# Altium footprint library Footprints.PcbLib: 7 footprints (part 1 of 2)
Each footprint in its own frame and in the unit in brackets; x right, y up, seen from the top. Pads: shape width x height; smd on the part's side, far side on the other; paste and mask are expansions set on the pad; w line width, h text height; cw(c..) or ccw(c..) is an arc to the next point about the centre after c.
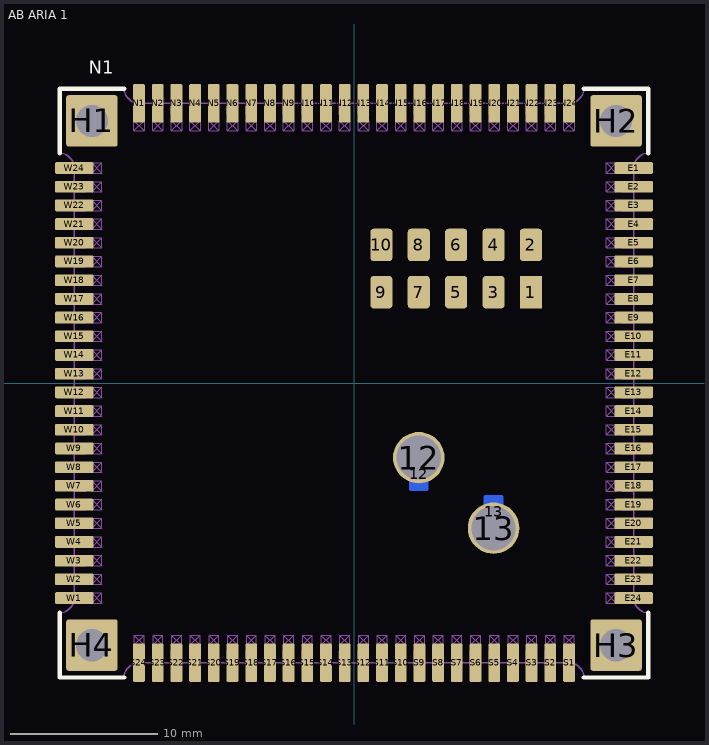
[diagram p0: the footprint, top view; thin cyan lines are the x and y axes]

## AB ARIA 1 [mm]
pads (114):
  rect 1.5x2.2 smd paste-0.2: 1(12.02,6.17)
  rrect30% 1.5x2.2 smd paste-0.2: 2(12.02,9.38) 3(9.48,6.17) 4(9.48,9.38) 5(6.94,6.17) 6(6.94,9.38) 7(4.4,6.17) 8(4.4,9.38) 9(1.86,6.17) 10(1.86,9.38)
  rrect20% 1.3x2.25 smd far side: 12(4.4,-6.195) 13(9.48,-8.735)
  round 3.5 hole 3 paste-1 mask+0.1: 12(4.4,-5.07) 13(9.48,-9.86)
  rrect20% 2.6x0.8 smd paste+0.05: E1(19,14.605) E2(19,13.335) E3(19,12.065) E4(19,10.795) E5(19,9.525) E6(19,8.255) E7(19,6.985) E8(19,5.715) E9(19,4.445) E10(19,3.175) E11(19,1.905) E12(19,0.635) E13(19,-0.635) E14(19,-1.905) E15(19,-3.175) E16(19,-4.445) E17(19,-5.715) E18(19,-6.985) E19(19,-8.255) E20(19,-9.525) E21(19,-10.795) E22(19,-12.065) E23(19,-13.335) E24(19,-14.605) W1(-19,-14.605) W2(-19,-13.335) W3(-19,-12.065) W4(-19,-10.795) W5(-19,-9.525) W6(-19,-8.255) W7(-19,-6.985) W8(-19,-5.715) W9(-19,-4.445) W10(-19,-3.175) W11(-19,-1.905) W12(-19,-0.635) W13(-19,0.635) W14(-19,1.905) W15(-19,3.175) W16(-19,4.445) W17(-19,5.715) W18(-19,6.985) W19(-19,8.255) W20(-19,9.525) W21(-19,10.795) W22(-19,12.065) W23(-19,13.335) W24(-19,14.605)
  rrect10% 3.5x3.5 hole 2.2 mask+0.2: H1(-17.8,17.8) H2(17.8,17.8) H3(17.8,-17.8) H4(-17.8,-17.8)
  rrect20% 0.8x2.6 smd paste+0.05: N1(-14.605,19) N2(-13.335,19) N3(-12.065,19) N4(-10.795,19) N5(-9.525,19) N6(-8.255,19) N7(-6.985,19) N8(-5.715,19) N9(-4.445,19) N10(-3.175,19) N11(-1.905,19) N12(-0.635,19) N13(0.635,19) N14(1.905,19) N15(3.175,19) N16(4.445,19) N17(5.715,19) N18(6.985,19) N19(8.255,19) N20(9.525,19) N21(10.795,19) N22(12.065,19) N23(13.335,19) N24(14.605,19) S1(14.605,-19) S2(13.335,-19) S3(12.065,-19) S4(10.795,-19) S5(9.525,-19) S6(8.255,-19) S7(6.985,-19) S8(5.715,-19) S9(4.445,-19) S10(3.175,-19) S11(1.905,-19) S12(0.635,-19) S13(-0.635,-19) S14(-1.905,-19) S15(-3.175,-19) S16(-4.445,-19) S17(-5.715,-19) S18(-6.985,-19) S19(-8.255,-19) S20(-9.525,-19) S21(-10.795,-19) S22(-12.065,-19) S23(-13.335,-19) S24(-14.605,-19)
Top Overlay:
  lines w0.3: -20,-15.605 -20,-20 ; -20,15.605 -20,20 -15.605,20 ; -15.605,-20 -20,-20 ; 15.605,-20 20,-20 20,-15.605 ; 15.605,20 20,20 ; 20,15.605 20,20 ; -20,-20 -20,-20 ; -15.605,20 -15.605,20 ; 20,20 20,20
  text "N1" at -18.034,20.701 h1.52
Top Paste:
  lines w0.8: -20.75,-14.61 -20.45,-14.61 ; -20.75,-13.34 -20.45,-13.34 ; -20.75,-12.07 -20.45,-12.07 ; -20.75,-10.8 -20.45,-10.8 ; -20.75,-9.53 -20.45,-9.53 ; -20.75,-8.26 -20.45,-8.26 ; -20.75,-6.99 -20.45,-6.99 ; -20.75,-5.72 -20.45,-5.72 ; -20.75,-4.45 -20.45,-4.45 ; -20.75,-3.18 -20.45,-3.18 ; -20.75,-1.91 -20.45,-1.91 ; -20.75,-0.64 -20.45,-0.64 ; -20.75,0.63 -20.45,0.63 ; -20.75,1.9 -20.45,1.9 ; -20.75,3.17 -20.45,3.17 ; -20.75,4.44 -20.45,4.44 ; -20.75,5.71 -20.45,5.71 ; -20.75,6.98 -20.45,6.98 ; -20.75,8.25 -20.45,8.25 ; -20.75,9.52 -20.45,9.52 ; -20.75,10.79 -20.45,10.79 ; -20.75,12.06 -20.45,12.06 ; -20.75,13.33 -20.45,13.33 ; -20.75,14.6 -20.45,14.6 ; -14.61,20.45 -14.61,20.75 ; -14.6,-20.75 -14.6,-20.45 ; -13.34,20.45 -13.34,20.75 ; -13.33,-20.75 -13.33,-20.45 ; -12.07,20.45 -12.07,20.75 ; -12.06,-20.75 -12.06,-20.45 ; -10.8,20.45 -10.8,20.75 ; -10.79,-20.75 -10.79,-20.45 ; -9.53,20.45 -9.53,20.75 ; -9.52,-20.75 -9.52,-20.45 ; -8.26,20.45 -8.26,20.75 ; -8.25,-20.75 -8.25,-20.45 ; -6.99,20.45 -6.99,20.75 ; -6.98,-20.75 -6.98,-20.45 ; -5.72,20.45 -5.72,20.75 ; -5.71,-20.75 -5.71,-20.45 ; -4.45,20.45 -4.45,20.75 ; -4.44,-20.75 -4.44,-20.45 ; -3.18,20.45 -3.18,20.75 ; -3.17,-20.75 -3.17,-20.45 ; -1.91,20.45 -1.91,20.75 ; -1.9,-20.75 -1.9,-20.45 ; -0.64,20.45 -0.64,20.75 ; -0.63,-20.75 -0.63,-20.45 ; 0.63,20.45 0.63,20.75 ; 0.64,-20.75 0.64,-20.45 ; 1.9,20.45 1.9,20.75 ; 1.91,-20.75 1.91,-20.45 ; 3.17,20.45 3.17,20.75 ; 3.18,-20.75 3.18,-20.45 ; 4.44,20.45 4.44,20.75 ; 4.45,-20.75 4.45,-20.45 ; 5.71,20.45 5.71,20.75 ; 5.72,-20.75 5.72,-20.45 ; 6.98,20.45 6.98,20.75 ; 6.99,-20.75 6.99,-20.45 ; 8.25,20.45 8.25,20.75 ; 8.26,-20.75 8.26,-20.45 ; 9.52,20.45 9.52,20.75 ; 9.53,-20.75 9.53,-20.45 ; 10.79,20.45 10.79,20.75 ; 10.8,-20.75 10.8,-20.45 ; 12.06,20.45 12.06,20.75 ; 12.07,-20.75 12.07,-20.45 ; 13.33,20.45 13.33,20.75 ; 13.34,-20.75 13.34,-20.45 ; 14.6,20.45 14.6,20.75 ; 14.61,-20.75 14.61,-20.45 ; 20.45,-14.6 20.75,-14.6 ; 20.45,-13.33 20.75,-13.33 ; 20.45,-12.06 20.75,-12.06 ; 20.45,-10.79 20.75,-10.79 ; 20.45,-9.52 20.75,-9.52 ; 20.45,-8.25 20.75,-8.25 ; 20.45,-6.98 20.75,-6.98 ; 20.45,-5.71 20.75,-5.71 ; 20.45,-4.44 20.75,-4.44 ; 20.45,-3.17 20.75,-3.17 ; 20.45,-1.9 20.75,-1.9 ; 20.45,-0.63 20.75,-0.63 ; 20.45,0.64 20.75,0.64 ; 20.45,1.91 20.75,1.91 ; 20.45,3.18 20.75,3.18 ; 20.45,4.45 20.75,4.45 ; 20.45,5.72 20.75,5.72 ; 20.45,6.99 20.75,6.99 ; 20.45,8.26 20.75,8.26 ; 20.45,9.53 20.75,9.53 ; 20.45,10.8 20.75,10.8 ; 20.45,12.07 20.75,12.07 ; 20.45,13.34 20.75,13.34 ; 20.45,14.61 20.75,14.61
Bottom Solder:
  region: 10.155,7.199 8.79,7.199 8.79,5.161 10.155,5.161
  region: 10.164,10.397 8.799,10.397 8.799,8.359 10.164,8.359
  region: 12.701,10.397 11.336,10.397 11.336,8.359 12.701,8.359
Mechanical 1:
  lines w0.1: 14.605,-19 cw(c14.605,-20) 15.605,-20 20,-20 20,-15.605 cw(c20,-14.605) 19,-14.605 19,14.605 cw(c20,14.605) 20,15.605 20,20 15.605,20 cw(c14.605,20) 14.605,19 -14.605,19 cw(c-14.605,20) -15.605,20 -20,20 -20,15.605 cw(c-20,14.605) -19,14.605 -19,-14.605 cw(c-20,-14.605) -20,-15.605 -20,-20 -15.605,-20 cw(c-14.605,-20) -14.605,-19 14.655,-19
Mechanical 15:
  drawing of 1308 lines, arcs and shapes, not listed
3D body "Aria.step": height 2.75, standoff 0.01, extent -20.055,-20.055 20.054,20.054
3D body: height 0.02, standoff -0.03, extent 8.786,-9.433 10.18,-8.036
3D body: height 0.02, standoff -0.03, extent 3.706,-6.893 5.1,-5.496
3D body: height 0.1, standoff 0.01, extent 1.21,5.17 2.51,7.17
3D body: height 0.1, standoff 0.01, extent 3.75,5.17 5.05,7.17
3D body: height 0.1, standoff 0.01, extent 6.29,5.17 7.59,7.17
3D body: height 0.1, standoff 0.01, extent 8.83,5.17 10.13,7.17
3D body: height 0.1, standoff 0.01, extent 11.37,5.17 12.67,7.17
3D body: height 0.1, standoff 0.01, extent 1.21,8.38 2.51,10.38
3D body: height 0.1, standoff 0.01, extent 3.75,8.38 5.05,10.38
3D body: height 0.1, standoff 0.01, extent 6.29,8.38 7.59,10.38
3D body: height 0.1, standoff 0.01, extent 8.83,8.38 10.13,10.38
3D body: height 0.1, standoff 0.01, extent 11.37,8.38 12.67,10.38
3D body: height 1.51, standoff 0.01, extent -0.64,13.7 0.72,15.27
3D body: height 1.51, standoff 0.01, extent -1.599,16 1.6,17.6
3D body: height 1.51, standoff 1.4, extent 17.82,14.255 19.05,14.955
3D body: height 0.1, standoff 0.01, extent 17.12,14.255 17.82,14.955
3D body: height 1.4, standoff 0.01, extent 18.23,14.255 19.05,14.955
3D body: height 1.4, standoff 0.01, extent 18.23,12.985 19.05,13.685
3D body: height 0.1, standoff 0.01, extent 17.12,12.985 17.82,13.685
3D body: height 1.51, standoff 1.4, extent 18.23,12.985 19.05,13.685
3D body: height 1.4, standoff 0.01, extent 18.23,11.715 19.05,12.415
3D body: height 0.1, standoff 0.01, extent 17.12,11.715 17.82,12.415
3D body: height 1.51, standoff 1.4, extent 18.23,11.715 19.05,12.415
3D body: height 1.4, standoff 0.01, extent 18.23,10.445 19.05,11.145
3D body: height 0.1, standoff 0.01, extent 17.12,10.445 17.82,11.145
3D body: height 1.51, standoff 1.4, extent 18.23,10.445 19.05,11.145
3D body: height 1.4, standoff 0.01, extent 18.23,9.175 19.05,9.875
3D body: height 0.1, standoff 0.01, extent 17.12,9.175 17.82,9.875
3D body: height 1.51, standoff 1.4, extent 18.23,9.175 19.05,9.875
3D body: height 1.4, standoff 0.01, extent 18.23,7.905 19.05,8.605
3D body: height 0.1, standoff 0.01, extent 17.12,7.905 17.82,8.605
3D body: height 1.51, standoff 1.4, extent 18.23,7.905 19.05,8.605
3D body: height 1.4, standoff 0.01, extent 18.23,6.635 19.05,7.335
3D body: height 0.1, standoff 0.01, extent 17.12,6.635 17.82,7.335
3D body: height 1.51, standoff 1.4, extent 18.23,6.635 19.05,7.335
3D body: height 1.4, standoff 0.01, extent 18.23,5.365 19.05,6.065
3D body: height 0.1, standoff 0.01, extent 17.12,5.365 17.82,6.065
3D body: height 1.51, standoff 1.4, extent 18.23,5.365 19.05,6.065
3D body: height 1.4, standoff 0.01, extent 18.23,4.095 19.05,4.795
3D body: height 0.1, standoff 0.01, extent 17.12,4.095 17.82,4.795
3D body: height 1.51, standoff 1.4, extent 18.23,4.095 19.05,4.795
3D body: height 1.4, standoff 0.01, extent 18.23,2.825 19.05,3.525
3D body: height 0.1, standoff 0.01, extent 17.12,2.825 17.82,3.525
3D body: height 1.51, standoff 1.4, extent 18.23,2.825 19.05,3.525
3D body: height 1.4, standoff 0.01, extent 18.23,1.555 19.05,2.255
3D body: height 0.1, standoff 0.01, extent 17.12,1.555 17.82,2.255
3D body: height 1.51, standoff 1.4, extent 18.23,1.555 19.05,2.255
3D body: height 1.4, standoff 0.01, extent 18.23,0.285 19.05,0.985
3D body: height 0.1, standoff 0.01, extent 17.12,0.285 17.82,0.985
3D body: height 1.51, standoff 1.4, extent 18.23,0.285 19.05,0.985
3D body: height 1.4, standoff 0.01, extent 18.23,-0.985 19.05,-0.285
3D body: height 0.1, standoff 0.01, extent 17.12,-0.985 17.82,-0.285
3D body: height 1.51, standoff 1.4, extent 18.23,-0.985 19.05,-0.285
3D body: height 1.4, standoff 0.01, extent 18.23,-2.255 19.05,-1.555
3D body: height 0.1, standoff 0.01, extent 17.12,-2.255 17.82,-1.555
3D body: height 1.51, standoff 1.4, extent 18.23,-2.255 19.05,-1.555
3D body: height 1.4, standoff 0.01, extent 18.23,-3.525 19.05,-2.825
3D body: height 0.1, standoff 0.01, extent 17.12,-3.525 17.82,-2.825
3D body: height 1.51, standoff 1.4, extent 18.23,-3.525 19.05,-2.825
3D body: height 1.4, standoff 0.01, extent 18.23,-4.795 19.05,-4.095
3D body: height 0.1, standoff 0.01, extent 17.12,-4.795 17.82,-4.095
3D body: height 1.51, standoff 1.4, extent 18.23,-4.795 19.05,-4.095
3D body: height 1.4, standoff 0.01, extent 18.23,-6.065 19.05,-5.365
3D body: height 0.1, standoff 0.01, extent 17.12,-6.065 17.82,-5.365
3D body: height 1.51, standoff 1.4, extent 18.23,-6.065 19.05,-5.365
3D body: height 1.4, standoff 0.01, extent 18.23,-7.335 19.05,-6.635
3D body: height 0.1, standoff 0.01, extent 17.12,-7.335 17.82,-6.635
3D body: height 1.51, standoff 1.4, extent 18.23,-7.335 19.05,-6.635
3D body: height 1.4, standoff 0.01, extent 18.23,-8.605 19.05,-7.905
3D body: height 0.1, standoff 0.01, extent 17.12,-8.605 17.82,-7.905
3D body: height 1.51, standoff 1.4, extent 18.23,-8.605 19.05,-7.905
3D body: height 1.4, standoff 0.01, extent 18.23,-9.875 19.05,-9.175
3D body: height 0.1, standoff 0.01, extent 17.12,-9.875 17.82,-9.175
3D body: height 1.51, standoff 1.4, extent 18.23,-9.875 19.05,-9.175
3D body: height 1.4, standoff 0.01, extent 18.23,-11.145 19.05,-10.445
3D body: height 0.1, standoff 0.01, extent 17.12,-11.145 17.82,-10.445
3D body: height 1.51, standoff 1.4, extent 18.23,-11.145 19.05,-10.445
3D body: height 1.4, standoff 0.01, extent 18.23,-12.415 19.05,-11.715
3D body: height 0.1, standoff 0.01, extent 17.12,-12.415 17.82,-11.715
3D body: height 1.51, standoff 1.4, extent 18.23,-12.415 19.05,-11.715
3D body: height 1.4, standoff 0.01, extent 18.23,-13.685 19.05,-12.985
3D body: height 0.1, standoff 0.01, extent 17.12,-13.685 17.82,-12.985
3D body: height 1.51, standoff 1.4, extent 18.23,-13.685 19.05,-12.985
3D body: height 1.4, standoff 0.01, extent 18.23,-14.955 19.05,-14.255
3D body: height 0.1, standoff 0.01, extent 17.12,-14.955 17.82,-14.255
3D body: height 1.51, standoff 1.4, extent 18.23,-14.955 19.05,-14.255
3D body: height 1.4, standoff 0.01, extent 14.255,-19.05 14.955,-18.23
3D body: height 0.1, standoff 0.01, extent 14.255,-17.82 14.955,-17.12
3D body: height 1.51, standoff 1.4, extent 14.255,-19.05 14.955,-17.82
3D body: height 1.4, standoff 0.01, extent 12.985,-19.05 13.685,-18.23
3D body: height 0.1, standoff 0.01, extent 12.985,-17.82 13.685,-17.12
3D body: height 1.51, standoff 1.4, extent 12.985,-19.05 13.685,-18.23
3D body: height 1.4, standoff 0.01, extent 11.715,-19.05 12.415,-18.23
3D body: height 0.1, standoff 0.01, extent 11.715,-17.82 12.415,-17.12
3D body: height 1.51, standoff 1.4, extent 11.715,-19.05 12.415,-18.23
3D body: height 1.4, standoff 0.01, extent 10.445,-19.05 11.145,-18.23
3D body: height 0.1, standoff 0.01, extent 10.445,-17.82 11.145,-17.12
3D body: height 1.51, standoff 1.4, extent 10.445,-19.05 11.145,-18.23
3D body: height 1.4, standoff 0.01, extent 9.175,-19.05 9.875,-18.23
3D body: height 0.1, standoff 0.01, extent 9.175,-17.82 9.875,-17.12
3D body: height 1.51, standoff 1.4, extent 9.175,-19.05 9.875,-18.23
3D body: height 1.4, standoff 0.01, extent 7.905,-19.05 8.605,-18.23
3D body: height 0.1, standoff 0.01, extent 7.905,-17.82 8.605,-17.12
3D body: height 1.51, standoff 1.4, extent 7.905,-19.05 8.605,-18.23
3D body: height 1.4, standoff 0.01, extent 6.635,-19.05 7.335,-18.23
3D body: height 0.1, standoff 0.01, extent 6.635,-17.82 7.335,-17.12
3D body: height 1.51, standoff 1.4, extent 6.635,-19.05 7.335,-18.23
3D body: height 1.4, standoff 0.01, extent 5.365,-19.05 6.065,-18.23
3D body: height 0.1, standoff 0.01, extent 5.365,-17.82 6.065,-17.12
3D body: height 1.51, standoff 1.4, extent 5.365,-19.05 6.065,-18.23
3D body: height 1.4, standoff 0.01, extent 4.095,-19.05 4.795,-18.23
3D body: height 0.1, standoff 0.01, extent 4.095,-17.82 4.795,-17.12
3D body: height 1.51, standoff 1.4, extent 4.095,-19.05 4.795,-18.23
3D body: height 1.4, standoff 0.01, extent 2.825,-19.05 3.525,-18.23
3D body: height 0.1, standoff 0.01, extent 2.825,-17.82 3.525,-17.12
3D body: height 1.51, standoff 1.4, extent 2.825,-19.05 3.525,-18.23
3D body: height 1.4, standoff 0.01, extent 1.555,-19.05 2.255,-18.23
3D body: height 0.1, standoff 0.01, extent 1.555,-17.82 2.255,-17.12
3D body: height 1.51, standoff 1.4, extent 1.555,-19.05 2.255,-18.23
3D body: height 1.4, standoff 0.01, extent 0.285,-19.05 0.985,-18.23
3D body: height 0.1, standoff 0.01, extent 0.285,-17.82 0.985,-17.12
3D body: height 1.51, standoff 1.4, extent 0.285,-19.05 0.985,-18.23
3D body: height 1.4, standoff 0.01, extent -0.985,-19.05 -0.285,-18.23
3D body: height 0.1, standoff 0.01, extent -0.985,-17.82 -0.285,-17.12
3D body: height 1.51, standoff 1.4, extent -0.985,-19.05 -0.285,-18.23
3D body: height 1.4, standoff 0.01, extent -2.255,-19.05 -1.555,-18.23
3D body: height 0.1, standoff 0.01, extent -2.255,-17.82 -1.555,-17.12
3D body: height 1.51, standoff 1.4, extent -2.255,-19.05 -1.555,-18.23
3D body: height 1.4, standoff 0.01, extent -3.525,-19.05 -2.825,-18.23
3D body: height 0.1, standoff 0.01, extent -3.525,-17.82 -2.825,-17.12
3D body: height 1.51, standoff 1.4, extent -3.525,-19.05 -2.825,-18.23
3D body: height 1.4, standoff 0.01, extent -4.795,-19.05 -4.095,-18.23
3D body: height 0.1, standoff 0.01, extent -4.795,-17.82 -4.095,-17.12
3D body: height 1.51, standoff 1.4, extent -4.795,-19.05 -4.095,-18.23
3D body: height 1.4, standoff 0.01, extent -6.065,-19.05 -5.365,-18.23
3D body: height 0.1, standoff 0.01, extent -6.065,-17.82 -5.365,-17.12
3D body: height 1.51, standoff 1.4, extent -6.065,-19.05 -5.365,-18.23
3D body: height 1.4, standoff 0.01, extent -7.335,-19.05 -6.635,-18.23
3D body: height 0.1, standoff 0.01, extent -7.335,-17.82 -6.635,-17.12
3D body: height 1.51, standoff 1.4, extent -7.335,-19.05 -6.635,-18.23
3D body: height 1.4, standoff 0.01, extent -8.605,-19.05 -7.905,-18.23
3D body: height 0.1, standoff 0.01, extent -8.605,-17.82 -7.905,-17.12
3D body: height 1.51, standoff 1.4, extent -8.605,-19.05 -7.905,-18.23
3D body: height 1.4, standoff 0.01, extent -9.875,-19.05 -9.175,-18.23
3D body: height 0.1, standoff 0.01, extent -9.875,-17.82 -9.175,-17.12
3D body: height 1.51, standoff 1.4, extent -9.875,-19.05 -9.175,-18.23
3D body: height 1.4, standoff 0.01, extent -11.145,-19.05 -10.445,-18.23
3D body: height 0.1, standoff 0.01, extent -11.145,-17.82 -10.445,-17.12
3D body: height 1.51, standoff 1.4, extent -11.145,-19.05 -10.445,-18.23
3D body: height 1.4, standoff 0.01, extent -12.415,-19.05 -11.715,-18.23
3D body: height 0.1, standoff 0.01, extent -12.415,-17.82 -11.715,-17.12
3D body: height 1.51, standoff 1.4, extent -12.415,-19.05 -11.715,-18.23
3D body: height 1.4, standoff 0.01, extent -13.685,-19.05 -12.985,-18.23
3D body: height 0.1, standoff 0.01, extent -13.685,-17.82 -12.985,-17.12
3D body: height 1.51, standoff 1.4, extent -13.685,-19.05 -12.985,-18.23
3D body: height 1.4, standoff 0.01, extent -14.955,-19.05 -14.255,-18.23
3D body: height 0.1, standoff 0.01, extent -14.955,-17.82 -14.255,-17.12
3D body: height 1.51, standoff 1.4, extent -14.955,-19.05 -14.255,-18.23
3D body: height 1.4, standoff 0.01, extent -19.05,-14.955 -18.23,-14.255
3D body: height 0.1, standoff 0.01, extent -17.82,-14.955 -17.12,-14.255
3D body: height 1.51, standoff 1.4, extent -19.05,-14.955 -17.82,-14.255
3D body: height 1.4, standoff 0.01, extent -19.05,-13.685 -18.23,-12.985
3D body: height 0.1, standoff 0.01, extent -17.82,-13.685 -17.12,-12.985
3D body: height 1.51, standoff 1.4, extent -19.05,-13.685 -18.23,-12.985
3D body: height 1.4, standoff 0.01, extent -19.05,-12.415 -18.23,-11.715
3D body: height 0.1, standoff 0.01, extent -17.82,-12.415 -17.12,-11.715
3D body: height 1.51, standoff 1.4, extent -19.05,-12.415 -18.23,-11.715
3D body: height 1.4, standoff 0.01, extent -19.05,-11.145 -18.23,-10.445
3D body: height 0.1, standoff 0.01, extent -17.82,-11.145 -17.12,-10.445
3D body: height 1.51, standoff 1.4, extent -19.05,-11.145 -18.23,-10.445
3D body: height 1.4, standoff 0.01, extent -19.05,-9.875 -18.23,-9.175
3D body: height 0.1, standoff 0.01, extent -17.82,-9.875 -17.12,-9.175
3D body: height 1.51, standoff 1.4, extent -19.05,-9.875 -18.23,-9.175
3D body: height 1.4, standoff 0.01, extent -19.05,-8.605 -18.23,-7.905
3D body: height 0.1, standoff 0.01, extent -17.82,-8.605 -17.12,-7.905
3D body: height 1.51, standoff 1.4, extent -19.05,-8.605 -18.23,-7.905
3D body: height 1.4, standoff 0.01, extent -19.05,-7.335 -18.23,-6.635
3D body: height 0.1, standoff 0.01, extent -17.82,-7.335 -17.12,-6.635
3D body: height 1.51, standoff 1.4, extent -19.05,-7.335 -18.23,-6.635
3D body: height 1.4, standoff 0.01, extent -19.05,-6.065 -18.23,-5.365
3D body: height 0.1, standoff 0.01, extent -17.82,-6.065 -17.12,-5.365
3D body: height 1.51, standoff 1.4, extent -19.05,-6.065 -18.23,-5.365
3D body: height 1.4, standoff 0.01, extent -19.05,-4.795 -18.23,-4.095
3D body: height 0.1, standoff 0.01, extent -17.82,-4.795 -17.12,-4.095
3D body: height 1.51, standoff 1.4, extent -19.05,-4.795 -18.23,-4.095
3D body: height 1.4, standoff 0.01, extent -19.05,-3.525 -18.23,-2.825
3D body: height 0.1, standoff 0.01, extent -17.82,-3.525 -17.12,-2.825
3D body: height 1.51, standoff 1.4, extent -19.05,-3.525 -18.23,-2.825
3D body: height 1.4, standoff 0.01, extent -19.05,-2.255 -18.23,-1.555
3D body: height 0.1, standoff 0.01, extent -17.82,-2.255 -17.12,-1.555
3D body: height 1.51, standoff 1.4, extent -19.05,-2.255 -18.23,-1.555
3D body: height 1.4, standoff 0.01, extent -19.05,-0.985 -18.23,-0.285
3D body: height 0.1, standoff 0.01, extent -17.82,-0.985 -17.12,-0.285
3D body: height 1.51, standoff 1.4, extent -19.05,-0.985 -18.23,-0.285
3D body: height 1.4, standoff 0.01, extent -19.05,0.285 -18.23,0.985
3D body: height 0.1, standoff 0.01, extent -17.82,0.285 -17.12,0.985
3D body: height 1.51, standoff 1.4, extent -19.05,0.285 -18.23,0.985
3D body: height 1.4, standoff 0.01, extent -19.05,1.555 -18.23,2.255
3D body: height 0.1, standoff 0.01, extent -17.82,1.555 -17.12,2.255
3D body: height 1.51, standoff 1.4, extent -19.05,1.555 -18.23,2.255
3D body: height 1.4, standoff 0.01, extent -19.05,2.825 -18.23,3.525
3D body: height 0.1, standoff 0.01, extent -17.82,2.825 -17.12,3.525
3D body: height 1.51, standoff 1.4, extent -19.05,2.825 -18.23,3.525
3D body: height 1.4, standoff 0.01, extent -19.05,4.095 -18.23,4.795
3D body: height 0.1, standoff 0.01, extent -17.82,4.095 -17.12,4.795
3D body: height 1.51, standoff 1.4, extent -19.05,4.095 -18.23,4.795
3D body: height 1.4, standoff 0.01, extent -19.05,5.365 -18.23,6.065
3D body: height 0.1, standoff 0.01, extent -17.82,5.365 -17.12,6.065
3D body: height 1.51, standoff 1.4, extent -19.05,5.365 -18.23,6.065
3D body: height 1.4, standoff 0.01, extent -19.05,6.635 -18.23,7.335
3D body: height 0.1, standoff 0.01, extent -17.82,6.635 -17.12,7.335
3D body: height 1.51, standoff 1.4, extent -19.05,6.635 -18.23,7.335
3D body: height 1.4, standoff 0.01, extent -19.05,7.905 -18.23,8.605
3D body: height 0.1, standoff 0.01, extent -17.82,7.905 -17.12,8.605
3D body: height 1.51, standoff 1.4, extent -19.05,7.905 -18.23,8.605
3D body: height 1.4, standoff 0.01, extent -19.05,9.175 -18.23,9.875
3D body: height 0.1, standoff 0.01, extent -17.82,9.175 -17.12,9.875
3D body: height 1.51, standoff 1.4, extent -19.05,9.175 -18.23,9.875
3D body: height 1.4, standoff 0.01, extent -19.05,10.445 -18.23,11.145
3D body: height 0.1, standoff 0.01, extent -17.82,10.445 -17.12,11.145
3D body: height 1.51, standoff 1.4, extent -19.05,10.445 -18.23,11.145
3D body: height 1.4, standoff 0.01, extent -19.05,11.715 -18.23,12.415
3D body: height 0.1, standoff 0.01, extent -17.82,11.715 -17.12,12.415
3D body: height 1.51, standoff 1.4, extent -19.05,11.715 -18.23,12.415
3D body: height 1.4, standoff 0.01, extent -19.05,12.985 -18.23,13.685
3D body: height 0.1, standoff 0.01, extent -17.82,12.985 -17.12,13.685
3D body: height 1.51, standoff 1.4, extent -19.05,12.985 -18.23,13.685
3D body: height 1.4, standoff 0.01, extent -19.05,14.255 -18.23,14.955
3D body: height 0.1, standoff 0.01, extent -17.82,14.255 -17.12,14.955
3D body: height 1.51, standoff 1.4, extent -19.05,14.255 -18.23,14.955
3D body: height 1.4, standoff 0.01, extent -14.955,18.23 -14.255,19.05
3D body: height 0.1, standoff 0.01, extent -14.955,17.12 -14.255,17.82
3D body: height 1.51, standoff 1.4, extent -14.955,17.82 -14.255,19.05
3D body: height 1.4, standoff 0.01, extent -13.685,18.23 -12.985,19.05
3D body: height 0.1, standoff 0.01, extent -13.685,17.12 -12.985,17.82
3D body: height 1.51, standoff 1.4, extent -13.685,18.23 -12.985,19.05
3D body: height 1.4, standoff 0.01, extent -12.415,18.23 -11.715,19.05
3D body: height 0.1, standoff 0.01, extent -12.415,17.12 -11.715,17.82
3D body: height 1.51, standoff 1.4, extent -12.415,18.23 -11.715,19.05
3D body: height 1.4, standoff 0.01, extent -11.145,18.23 -10.445,19.05
3D body: height 0.1, standoff 0.01, extent -11.145,17.12 -10.445,17.82
3D body: height 1.51, standoff 1.4, extent -11.145,18.23 -10.445,19.05
3D body: height 1.4, standoff 0.01, extent -9.875,18.23 -9.175,19.05
3D body: height 0.1, standoff 0.01, extent -9.875,17.12 -9.175,17.82
3D body: height 1.51, standoff 1.4, extent -9.875,18.23 -9.175,19.05
3D body: height 1.4, standoff 0.01, extent -8.605,18.23 -7.905,19.05
3D body: height 0.1, standoff 0.01, extent -8.605,17.12 -7.905,17.82
3D body: height 1.51, standoff 1.4, extent -8.605,18.23 -7.905,19.05
3D body: height 1.4, standoff 0.01, extent -7.335,18.23 -6.635,19.05
3D body: height 0.1, standoff 0.01, extent -7.335,17.12 -6.635,17.82
3D body: height 1.51, standoff 1.4, extent -7.335,18.23 -6.635,19.05
3D body: height 1.4, standoff 0.01, extent -6.065,18.23 -5.365,19.05
3D body: height 0.1, standoff 0.01, extent -6.065,17.12 -5.365,17.82
3D body: height 1.51, standoff 1.4, extent -6.065,18.23 -5.365,19.05
3D body: height 1.51, standoff 1.4, extent -4.795,18.23 -4.095,19.05
3D body: height 0.1, standoff 0.01, extent -4.795,17.12 -4.095,17.82
3D body: height 1.4, standoff 0.01, extent -4.795,18.23 -4.095,19.05
3D body: height 1.51, standoff 1.4, extent -3.525,18.23 -2.825,19.05
3D body: height 0.1, standoff 0.01, extent -3.525,17.12 -2.825,17.82
3D body: height 1.4, standoff 0.01, extent -3.525,18.23 -2.825,19.05
3D body: height 1.51, standoff 1.4, extent -2.255,18.23 -1.555,19.05
3D body: height 0.1, standoff 0.01, extent -2.255,17.12 -1.555,17.82
3D body: height 1.4, standoff 0.01, extent -2.255,18.23 -1.555,19.05
3D body: height 1.51, standoff 1.4, extent -0.985,18.23 -0.285,19.05
3D body: height 0.1, standoff 0.01, extent -0.985,17.12 -0.285,17.82
3D body: height 1.4, standoff 0.01, extent -0.985,18.23 -0.285,19.05
3D body: height 1.51, standoff 1.4, extent 0.285,18.23 0.985,19.05
3D body: height 0.1, standoff 0.01, extent 0.285,17.12 0.985,17.82
3D body: height 1.4, standoff 0.01, extent 0.285,18.23 0.985,19.05
3D body: height 1.51, standoff 1.4, extent 1.555,18.23 2.255,19.05
3D body: height 0.1, standoff 0.01, extent 1.555,17.12 2.255,17.82
3D body: height 1.4, standoff 0.01, extent 1.555,18.23 2.255,19.05
3D body: height 1.51, standoff 1.4, extent 2.825,18.23 3.525,19.05
3D body: height 0.1, standoff 0.01, extent 2.825,17.12 3.525,17.82
3D body: height 1.4, standoff 0.01, extent 2.825,18.23 3.525,19.05
3D body: height 1.51, standoff 1.4, extent 4.095,18.23 4.795,19.05
3D body: height 0.1, standoff 0.01, extent 4.095,17.12 4.795,17.82
3D body: height 1.4, standoff 0.01, extent 4.095,18.23 4.795,19.05
3D body: height 1.51, standoff 1.4, extent 5.365,18.23 6.065,19.05
3D body: height 0.1, standoff 0.01, extent 5.365,17.12 6.065,17.82
3D body: height 1.4, standoff 0.01, extent 5.365,18.23 6.065,19.05
3D body: height 1.51, standoff 1.4, extent 6.635,18.23 7.335,19.05
3D body: height 0.1, standoff 0.01, extent 6.635,17.12 7.335,17.82
3D body: height 1.4, standoff 0.01, extent 6.635,18.23 7.335,19.05
3D body: height 1.51, standoff 1.4, extent 7.905,18.23 8.605,19.05
3D body: height 0.1, standoff 0.01, extent 7.905,17.12 8.605,17.82
3D body: height 1.4, standoff 0.01, extent 7.905,18.23 8.605,19.05
3D body: height 1.51, standoff 1.4, extent 14.255,18.23 14.955,19.05
3D body: height 0.1, standoff 0.01, extent 14.255,17.12 14.955,17.82
3D body: height 1.4, standoff 0.01, extent 14.255,18.23 14.955,19.05
3D body: height 1.51, standoff 1.4, extent 12.985,18.23 13.685,19.05
3D body: height 0.1, standoff 0.01, extent 12.985,17.12 13.685,17.82
3D body: height 1.4, standoff 0.01, extent 12.985,18.23 13.685,19.05
3D body: height 1.51, standoff 1.4, extent 11.715,18.23 12.415,19.05
3D body: height 0.1, standoff 0.01, extent 11.715,17.12 12.415,17.82
3D body: height 1.4, standoff 0.01, extent 11.715,18.23 12.415,19.05
3D body: height 1.51, standoff 1.4, extent 10.445,18.23 11.145,19.05
3D body: height 0.1, standoff 0.01, extent 10.445,17.12 11.145,17.82
3D body: height 1.4, standoff 0.01, extent 10.445,18.23 11.145,19.05
3D body: height 1.51, standoff 1.4, extent 9.175,18.23 9.875,19.05
3D body: height 0.1, standoff 0.01, extent 9.175,17.12 9.875,17.82
3D body: height 1.4, standoff 0.01, extent 9.175,18.23 9.875,19.05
